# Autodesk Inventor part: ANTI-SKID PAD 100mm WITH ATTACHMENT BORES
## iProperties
Created: 2007-03
Part Number: ANTI-SKID PAD 100mm WITH ATTACHMENT BORES
Material: Rubber
Document SubType Name: Modeling
Designer: Andy Moles
Density: 0.93 g/cm^3
Author: Andy Moles
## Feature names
1. Extrusion1
2. Extrusion2
3. Fillet1
